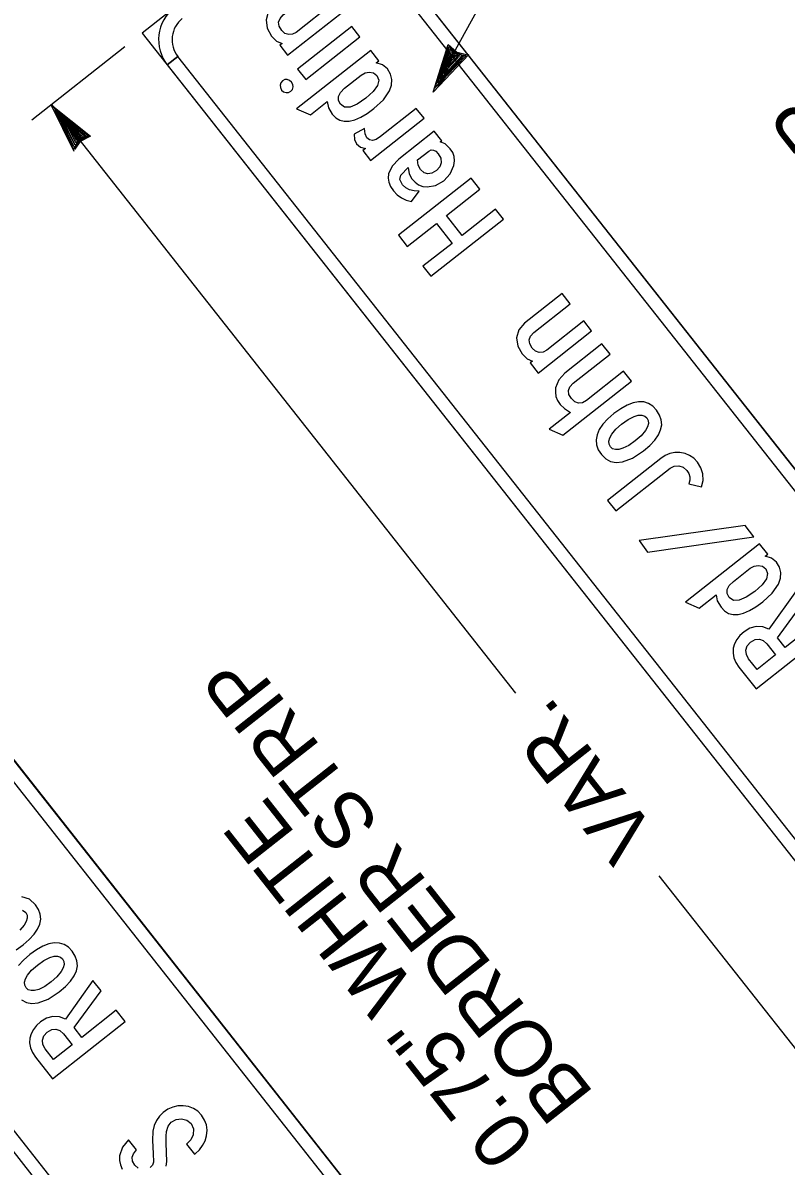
# Model space of a CAD drawing. Extents: x 672438 to 673980, y 1673259 to 1674850.
# Drawn here: x 673725.7 to 673782.3, y 1673411.9 to 1673496.8 of the extents above; entities that cross this region are included whole.
import ezdxf

# ---------------------------------------------------------------- set-up
doc = ezdxf.new("R2010")
doc.units = 0
doc.layers.add('C-ANNO-SYMB', color=7, linetype='Continuous')
doc.layers.add('Level 1', color=7, linetype='Continuous')

msp = doc.modelspace()

# ---------------------------------------------------------------- linework, layer by layer
at = {"layer": 'C-ANNO-SYMB'}
for p, q in [((673748.669, 1673507.161), (673734.534, 1673496.017)), ((673826.676, 1673408.211), (673748.669, 1673507.161)), ((673750.527, 1673504.805), (673824.819, 1673410.567)), ((673824.033, 1673409.948), (673749.741, 1673504.186)), ((673734.534, 1673496.017), (673812.54, 1673397.068)), ((673736.391, 1673493.661), (673737.176, 1673494.28)), ((673737.176, 1673494.28), (673736.391, 1673493.661)), ((673736.391, 1673493.661), (673810.683, 1673399.424)), ((673737.176, 1673494.28), (673737.176, 1673494.28)), ((673737.176, 1673494.28), (673737.176, 1673494.28)), ((673811.468, 1673400.043), (673737.176, 1673494.28)), ((673780.412, 1673371.74), (673702.406, 1673470.689)), ((673704.263, 1673468.333), (673778.555, 1673374.095)), ((673777.77, 1673373.476), (673703.478, 1673467.714)), ((673688.27, 1673459.545), (673766.277, 1673360.596)), ((673690.127, 1673457.189), (673764.42, 1673362.952)), ((673765.205, 1673363.571), (673690.913, 1673457.808))]:
    msp.add_line(p, q, dxfattribs=at)
for points in [[(673749.295, 1673497.493), (673748.712, 1673498.232), (673745.967, 1673496.068), (673745.695, 1673495.921), (673745.404, 1673495.895), (673745.127, 1673495.992), (673744.888, 1673496.206), (673744.703, 1673496.526), (673744.659, 1673496.827), (673744.76, 1673497.106), (673745.005, 1673497.367), (673747.712, 1673499.501), (673747.109, 1673500.265), (673744.318, 1673498.065), (673743.89, 1673497.575), (673743.721, 1673496.987), (673743.807, 1673496.366), (673744.134, 1673495.777), (673744.508, 1673495.419), (673744.91, 1673495.251), (673744.735, 1673495.113), (673745.326, 1673494.363)], [(673750.682, 1673495.733), (673750.082, 1673496.494), (673746.065, 1673493.328), (673746.665, 1673492.567)], [(673745.563, 1673491.698), (673745.682, 1673491.836), (673745.73, 1673492.014), (673745.711, 1673492.2), (673745.62, 1673492.37), (673745.475, 1673492.503), (673745.299, 1673492.57), (673745.119, 1673492.564), (673744.95, 1673492.476), (673744.825, 1673492.332), (673744.769, 1673492.152), (673744.788, 1673491.961), (673744.88, 1673491.786), (673745.028, 1673491.656), (673745.211, 1673491.599), (673745.399, 1673491.611)], [(673755.449, 1673489.687), (673754.866, 1673490.426), (673752.214, 1673488.324), (673751.904, 1673488.123), (673751.632, 1673488.04), (673751.401, 1673488.077), (673751.207, 1673488.236), (673751.07, 1673488.532), (673751.04, 1673488.926), (673750.272, 1673488.514), (673750.287, 1673488.105), (673750.424, 1673487.798), (673750.73, 1673487.543), (673751.093, 1673487.452), (673750.897, 1673487.297), (673751.48, 1673486.557)], [(673761.343, 1673482.21), (673760.76, 1673482.95), (673758.286, 1673480.999), (673757.119, 1673482.48), (673759.593, 1673484.43), (673758.943, 1673485.254), (673753.552, 1673481.004), (673754.202, 1673480.18), (673756.364, 1673481.885), (673757.531, 1673480.404), (673755.369, 1673478.7), (673755.952, 1673477.96)], [(673767.887, 1673473.91), (673767.304, 1673474.649), (673764.559, 1673472.485), (673764.286, 1673472.338), (673763.996, 1673472.312), (673763.718, 1673472.409), (673763.48, 1673472.624), (673763.295, 1673472.944), (673763.251, 1673473.244), (673763.351, 1673473.523), (673763.596, 1673473.784), (673766.303, 1673475.918), (673765.701, 1673476.682), (673762.909, 1673474.482), (673762.481, 1673473.992), (673762.313, 1673473.404), (673762.399, 1673472.783), (673762.726, 1673472.194), (673763.099, 1673471.836), (673763.502, 1673471.668), (673763.327, 1673471.53), (673763.918, 1673470.781)], [(673765.903, 1673470.78), (673765.441, 1673470.28), (673765.212, 1673469.689), (673765.193, 1673469.364), (673765.242, 1673469.049), (673765.363, 1673468.744), (673765.554, 1673468.451), (673765.873, 1673468.138), (673766.306, 1673467.853), (673764.729, 1673466.609), (673765.751, 1673466.165), (673770.834, 1673470.172), (673770.251, 1673470.911), (673767.505, 1673468.747), (673767.203, 1673468.57), (673766.914, 1673468.533), (673766.643, 1673468.635), (673766.386, 1673468.879), (673766.206, 1673469.19), (673766.164, 1673469.484), (673766.265, 1673469.759), (673766.505, 1673470.016), (673769.25, 1673472.18), (673768.648, 1673472.944)], [(673776.038, 1673462.33), (673776.161, 1673462.796), (673776.137, 1673463.288), (673775.995, 1673463.75), (673775.735, 1673464.171), (673775.465, 1673464.455), (673775.161, 1673464.67), (673774.821, 1673464.809), (673774.441, 1673464.879), (673774.059, 1673464.878), (673773.693, 1673464.803), (673773.345, 1673464.659), (673773.015, 1673464.443), (673769.064, 1673461.328), (673769.681, 1673460.546), (673773.71, 1673463.722), (673774.017, 1673463.878), (673774.36, 1673463.894), (673774.69, 1673463.782), (673774.951, 1673463.554), (673775.094, 1673463.324), (673775.168, 1673463.081), (673775.173, 1673462.826), (673775.109, 1673462.558)], [(673779.934, 1673458.628), (673779.274, 1673459.465), (673771.414, 1673458.347), (673772.03, 1673457.474)]]:
    msp.add_lwpolyline(points, close=True, dxfattribs=at)
for points in [[(673752.095, 1673493.951), (673751.491, 1673494.717), (673745.989, 1673490.379), (673747.01, 1673489.942), (673748.259, 1673490.926), (673748.346, 1673490.472), (673748.626, 1673490), (673748.894, 1673489.73), (673749.193, 1673489.553), (673749.529, 1673489.466), (673749.899, 1673489.474), (673750.306, 1673489.569), (673750.746, 1673489.759), (673751.222, 1673490.038), (673751.728, 1673490.408), (673752.432, 1673491.061), (673752.881, 1673491.721), (673753.036, 1673492.156), (673753.061, 1673492.573), (673752.961, 1673492.971), (673752.732, 1673493.349), (673752.362, 1673493.658), (673751.906, 1673493.801), (673752.095, 1673493.951)], [(673750.793, 1673492.898), (673751.075, 1673493.058), (673751.381, 1673493.114), (673751.7, 1673493.056), (673751.942, 1673492.861), (673752.085, 1673492.515), (673751.995, 1673492.119), (673751.679, 1673491.676), (673751.133, 1673491.181), (673750.497, 1673490.744), (673749.967, 1673490.521), (673749.551, 1673490.517), (673749.24, 1673490.73), (673749.091, 1673491.019), (673749.091, 1673491.314), (673749.242, 1673491.611), (673749.543, 1673491.913), (673750.793, 1673492.898)], [(673756.766, 1673488.016), (673756.209, 1673488.723), (673753.584, 1673486.654), (673753.078, 1673486.134), (673752.818, 1673485.574), (673752.791, 1673485.254), (673752.84, 1673484.939), (673752.968, 1673484.622), (673753.174, 1673484.311), (673753.455, 1673484.012), (673753.77, 1673483.782), (673754.124, 1673483.619), (673754.511, 1673483.522), (673755.083, 1673484.29), (673754.708, 1673484.291), (673754.374, 1673484.368), (673754.091, 1673484.523), (673753.855, 1673484.751), (673753.663, 1673485.133), (673753.722, 1673485.471), (673754.26, 1673486.04), (673754.342, 1673485.564), (673754.531, 1673485.198), (673754.778, 1673484.94), (673755.047, 1673484.754), (673755.347, 1673484.637), (673755.669, 1673484.588), (673756.304, 1673484.695), (673756.922, 1673485.054), (673757.399, 1673485.566), (673757.66, 1673486.182), (673757.71, 1673486.524), (673757.681, 1673486.846), (673757.579, 1673487.148), (673757.399, 1673487.43), (673757.022, 1673487.799), (673756.657, 1673487.93), (673756.766, 1673488.016)], [(673754.969, 1673486.599), (673755.799, 1673487.253), (673755.969, 1673487.339), (673756.142, 1673487.333), (673756.321, 1673487.236), (673756.502, 1673487.047), (673756.687, 1673486.721), (673756.721, 1673486.392), (673756.614, 1673486.083), (673756.365, 1673485.814), (673756.034, 1673485.615), (673755.728, 1673485.559), (673755.449, 1673485.649), (673755.191, 1673485.883), (673755.022, 1673486.206), (673754.969, 1673486.599)], [(673769.545, 1673467.768), (673769.083, 1673467.368), (673768.717, 1673466.972), (673768.454, 1673466.582), (673768.285, 1673466.2), (673768.22, 1673465.822), (673768.25, 1673465.452), (673768.382, 1673465.087), (673768.61, 1673464.731), (673768.931, 1673464.414), (673769.298, 1673464.218), (673769.712, 1673464.143), (673770.17, 1673464.188), (673770.929, 1673464.469), (673771.73, 1673464.996), (673772.201, 1673465.401), (673772.569, 1673465.796), (673772.842, 1673466.185), (673773.01, 1673466.566), (673773.085, 1673466.939), (673773.057, 1673467.305), (673772.931, 1673467.663), (673772.706, 1673468.014), (673772.42, 1673468.311), (673772.101, 1673468.517), (673771.753, 1673468.629), (673771.37, 1673468.646), (673770.963, 1673468.568), (673770.52, 1673468.396), (673770.05, 1673468.13), (673769.545, 1673467.768)], [(673770.114, 1673466.991), (673770.594, 1673467.327), (673771.045, 1673467.557), (673771.35, 1673467.645), (673771.61, 1673467.655), (673771.823, 1673467.589), (673771.987, 1673467.445), (673772.09, 1673467.25), (673772.104, 1673467.028), (673772.038, 1673466.78), (673771.881, 1673466.507), (673771.564, 1673466.123), (673771.129, 1673465.737), (673770.659, 1673465.409), (673770.212, 1673465.192), (673769.912, 1673465.104), (673769.653, 1673465.095), (673769.442, 1673465.162), (673769.275, 1673465.307), (673769.178, 1673465.498), (673769.161, 1673465.717), (673769.228, 1673465.961), (673769.374, 1673466.231), (673769.692, 1673466.612), (673770.114, 1673466.991)], [(673780.958, 1673457.339), (673780.353, 1673458.106), (673774.852, 1673453.768), (673775.872, 1673453.33), (673777.121, 1673454.315), (673777.208, 1673453.861), (673777.489, 1673453.389), (673777.757, 1673453.118), (673778.056, 1673452.942), (673778.392, 1673452.855), (673778.761, 1673452.863), (673779.168, 1673452.958), (673779.609, 1673453.147), (673780.085, 1673453.427), (673780.591, 1673453.797), (673781.294, 1673454.45), (673781.744, 1673455.109), (673781.899, 1673455.545), (673781.924, 1673455.962), (673781.824, 1673456.359), (673781.595, 1673456.738), (673781.225, 1673457.047), (673780.768, 1673457.19), (673780.958, 1673457.339)], [(673779.656, 1673456.287), (673779.938, 1673456.447), (673780.244, 1673456.503), (673780.563, 1673456.445), (673780.805, 1673456.249), (673780.947, 1673455.903), (673780.857, 1673455.508), (673780.542, 1673455.065), (673779.995, 1673454.57), (673779.359, 1673454.133), (673778.83, 1673453.91), (673778.413, 1673453.906), (673778.103, 1673454.119), (673777.953, 1673454.408), (673777.953, 1673454.703), (673778.105, 1673455), (673778.406, 1673455.301), (673779.656, 1673456.287)], [(673785.482, 1673451.591), (673784.815, 1673452.437), (673782.248, 1673450.413), (673781.681, 1673451.133), (673783.691, 1673453.862), (673783.082, 1673454.635), (673781.042, 1673451.757), (673780.59, 1673451.942), (673780.092, 1673451.962), (673779.633, 1673451.835), (673779.201, 1673451.575), (673778.895, 1673451.297), (673778.659, 1673450.998), (673778.495, 1673450.683), (673778.4, 1673450.352), (673778.381, 1673449.998), (673778.445, 1673449.646), (673778.591, 1673449.297), (673778.819, 1673448.954), (673780.09, 1673447.341), (673785.482, 1673451.591)], [(673781.538, 1673449.853), (673780.164, 1673448.77), (673779.54, 1673449.561), (673779.37, 1673449.876), (673779.334, 1673450.207), (673779.441, 1673450.522), (673779.688, 1673450.794), (673780.023, 1673450.988), (673780.333, 1673451.032), (673780.624, 1673450.927), (673780.894, 1673450.671), (673781.538, 1673449.853)], [(673725.177, 1673427.973), (673725.687, 1673428.34), (673726.143, 1673428.735), (673726.503, 1673429.123), (673726.766, 1673429.505), (673726.929, 1673429.879), (673726.998, 1673430.247), (673726.968, 1673430.608), (673726.841, 1673430.961), (673726.616, 1673431.311), (673726.157, 1673431.724), (673725.608, 1673431.909)], [(673725.66, 1673430.915), (673725.885, 1673430.735), (673725.989, 1673430.539), (673726.002, 1673430.319), (673725.931, 1673430.069), (673725.769, 1673429.798), (673725.451, 1673429.413)], [(673725.566, 1673424.255), (673725.933, 1673424.059), (673726.348, 1673423.985), (673726.806, 1673424.029), (673727.565, 1673424.31), (673728.366, 1673424.837), (673728.836, 1673425.242), (673729.205, 1673425.637), (673729.477, 1673426.026), (673729.646, 1673426.407), (673729.721, 1673426.78), (673729.692, 1673427.146), (673729.566, 1673427.504), (673729.341, 1673427.855), (673729.056, 1673428.152), (673728.736, 1673428.358), (673728.388, 1673428.47), (673728.006, 1673428.487), (673727.598, 1673428.41), (673727.155, 1673428.237), (673726.685, 1673427.971), (673726.18, 1673427.61)], [(673726.18, 1673427.61), (673725.719, 1673427.209), (673725.353, 1673426.814)], [(673726.749, 1673426.832), (673727.23, 1673427.168), (673727.681, 1673427.398), (673727.986, 1673427.486), (673728.245, 1673427.497), (673728.459, 1673427.43), (673728.623, 1673427.286), (673728.726, 1673427.091), (673728.74, 1673426.869), (673728.673, 1673426.621), (673728.516, 1673426.348), (673728.2, 1673425.964), (673727.765, 1673425.578), (673727.295, 1673425.25), (673726.848, 1673425.033), (673726.547, 1673424.945), (673726.288, 1673424.937), (673726.078, 1673425.004), (673725.91, 1673425.148), (673725.813, 1673425.339), (673725.796, 1673425.558), (673725.864, 1673425.802), (673726.01, 1673426.073), (673726.327, 1673426.454), (673726.749, 1673426.832)], [(673733.276, 1673422.647), (673732.61, 1673423.492), (673730.043, 1673421.469), (673729.475, 1673422.189), (673731.486, 1673424.917), (673730.877, 1673425.69), (673728.837, 1673422.812), (673728.385, 1673422.998), (673727.887, 1673423.018), (673727.428, 1673422.891), (673726.995, 1673422.631), (673726.689, 1673422.352), (673726.454, 1673422.053), (673726.289, 1673421.739), (673726.195, 1673421.408), (673726.176, 1673421.053), (673726.24, 1673420.701), (673726.386, 1673420.352), (673726.613, 1673420.01), (673727.885, 1673418.396), (673733.276, 1673422.647)], [(673729.333, 1673420.909), (673727.959, 1673419.825), (673727.335, 1673420.617), (673727.164, 1673420.931), (673727.128, 1673421.262), (673727.236, 1673421.578), (673727.483, 1673421.85), (673727.817, 1673422.044), (673728.127, 1673422.088), (673728.419, 1673421.983), (673728.689, 1673421.726), (673729.333, 1673420.909)], [(673736.308, 1673411.902), (673736.372, 1673412.247), (673736.308, 1673413.617), (673736.299, 1673414.137), (673736.324, 1673414.484), (673736.453, 1673414.874), (673736.692, 1673415.162), (673737.052, 1673415.36), (673737.444, 1673415.42), (673737.843, 1673415.322), (673738.154, 1673415.063), (673738.343, 1673414.674), (673738.324, 1673414.244), (673738.148, 1673413.861), (673737.83, 1673413.539), (673738.417, 1673412.794), (673738.467, 1673412.833), (673738.777, 1673413.115), (673739.019, 1673413.432), (673739.194, 1673413.784), (673739.303, 1673414.169), (673739.344, 1673414.579), (673739.294, 1673414.969), (673739.16, 1673415.334), (673738.938, 1673415.681), (673738.656, 1673415.979), (673738.331, 1673416.197), (673737.973, 1673416.335), (673737.573, 1673416.395), (673737.182, 1673416.378), (673736.805, 1673416.29), (673736.444, 1673416.132), (673736.096, 1673415.9), (673735.809, 1673415.623), (673735.583, 1673415.298), (673735.422, 1673414.924), (673735.322, 1673414.505), (673735.292, 1673413.822), (673735.356, 1673412.857), (673735.372, 1673412.198), (673735.285, 1673411.985), (673735.129, 1673411.813)], [(673734.23, 1673411.759), (673733.987, 1673411.972), (673733.821, 1673412.274), (673733.796, 1673412.571), (673733.896, 1673412.82), (673734.103, 1673413.113), (673733.512, 1673413.862), (673733.058, 1673413.307), (673732.85, 1673412.679), (673732.847, 1673412.337), (673732.911, 1673412.005), (673733.05, 1673411.677)]]:
    msp.add_lwpolyline(points, dxfattribs=at)
for radius in [3, 2]:
    msp.add_arc((673738.747, 1673495.518), radius, 128.25054, 218.25075, dxfattribs=at)
at = {"layer": 'Level 1'}
for p, q in [((673756.128, 1673491.622), (673757.245, 1673495.172)), ((673757.245, 1673495.172), (673757.884, 1673494.605)), ((673733.247, 1673494.982), (673726.342, 1673489.539)), ((673758.783, 1673494.422), (673756.128, 1673491.622)), ((673756.246, 1673491.921), (673757.281, 1673495.027)), ((673758.414, 1673494.317), (673756.274, 1673491.966)), ((673758.582, 1673494.341), (673756.391, 1673492.109)), ((673756.475, 1673492.305), (673757.339, 1673494.869)), ((673756.643, 1673492.477), (673757.475, 1673494.637)), ((673758.275, 1673494.341), (673756.643, 1673492.477)), ((673756.665, 1673492.618), (673757.388, 1673494.747)), ((673758.275, 1673494.341), (673756.665, 1673492.618)), ((673756.947, 1673493.091), (673757.475, 1673494.483)), ((673758.087, 1673494.331), (673756.947, 1673493.091)), ((673757.212, 1673493.481), (673757.488, 1673494.351)), ((673757.921, 1673494.309), (673757.212, 1673493.481)), ((673757.281, 1673495.027), (673757.803, 1673494.623)), ((673757.525, 1673494.516), (673757.327, 1673493.626)), ((673757.339, 1673494.869), (673757.562, 1673494.676)), ((673757.388, 1673494.747), (673758.275, 1673494.341)), ((673757.803, 1673494.317), (673757.418, 1673493.878)), ((673757.475, 1673494.637), (673758.087, 1673494.331)), ((673757.475, 1673494.483), (673757.921, 1673494.309)), ((673757.488, 1673494.351), (673757.803, 1673494.317)), ((673757.974, 1673494.398), (673757.525, 1673494.516)), ((673757.562, 1673494.676), (673758.275, 1673494.341)), ((673757.644, 1673494.259), (673757.974, 1673494.398)), ((673757.803, 1673494.623), (673758.599, 1673494.423)), ((673757.884, 1673494.605), (673758.221, 1673494.403)), ((673758.221, 1673494.403), (673758.582, 1673494.341)), ((673758.372, 1673494.403), (673758.414, 1673494.317)), ((673757.327, 1673493.626), (673757.127, 1673493.441)), ((673757.418, 1673493.878), (673757.544, 1673494.29)), ((673757.544, 1673494.29), (673757.644, 1673494.259)), ((673756.457, 1673492.068), (673757.049, 1673492.752)), ((673757.049, 1673492.752), (673756.475, 1673492.305)), ((673757.127, 1673493.441), (673756.915, 1673492.986)), ((673756.915, 1673492.986), (673757.246, 1673493.337)), ((673729.49, 1673487.216), (673727.787, 1673490.678)), ((673727.787, 1673490.678), (673730.695, 1673488.356)), ((673762.257, 1673447.023), (673727.82, 1673490.704)), ((673728.146, 1673490.257), (673728.023, 1673490.46)), ((673728.023, 1673490.46), (673730.547, 1673488.375)), ((673729.476, 1673487.574), (673728.054, 1673490.418)), ((673728.054, 1673490.418), (673728.084, 1673490.211)), ((673728.084, 1673490.211), (673728.509, 1673489.411)), ((673729.438, 1673487.408), (673728.146, 1673490.257)), ((673728.509, 1673489.411), (673728.298, 1673490.109)), ((673728.298, 1673490.109), (673730.378, 1673488.377)), ((673729.548, 1673487.695), (673728.398, 1673489.89)), ((673728.398, 1673489.89), (673730.113, 1673488.335)), ((673729.548, 1673487.695), (673728.522, 1673489.818)), ((673728.522, 1673489.818), (673730.247, 1673488.376)), ((673729.123, 1673489.091), (673728.775, 1673489.452)), ((673728.775, 1673489.452), (673728.983, 1673489.017)), ((673729.607, 1673487.874), (673728.861, 1673489.384)), ((673728.861, 1673489.384), (673729.969, 1673488.39)), ((673729.223, 1673488.837), (673729.123, 1673489.091)), ((673729.647, 1673488.037), (673729.13, 1673488.997)), ((673729.13, 1673488.997), (673729.842, 1673488.425)), ((673729.981, 1673488.331), (673729.223, 1673488.837)), ((673729.696, 1673488.144), (673729.425, 1673488.661)), ((673729.425, 1673488.661), (673729.765, 1673488.395)), ((673730.247, 1673488.376), (673729.548, 1673487.695)), ((673729.969, 1673488.39), (673729.647, 1673488.037)), ((673729.842, 1673488.425), (673729.696, 1673488.144)), ((673729.765, 1673488.395), (673729.7, 1673488.313)), ((673730.547, 1673488.375), (673729.981, 1673488.034)), ((673730.378, 1673488.377), (673730.118, 1673488.239)), ((673729.626, 1673487.723), (673729.438, 1673487.408)), ((673729.572, 1673487.582), (673729.476, 1673487.574)), ((673729.981, 1673488.034), (673729.508, 1673487.363)), ((673730.118, 1673488.239), (673729.548, 1673487.695)), ((673730.113, 1673488.335), (673729.607, 1673487.874)), ((673729.936, 1673487.964), (673729.626, 1673487.723)), ((673729.7, 1673488.313), (673729.71, 1673487.956)), ((673729.71, 1673487.956), (673729.981, 1673488.331)), ((673730.695, 1673488.356), (673729.936, 1673487.964)), ((673805.784, 1673391.741), (673772.9, 1673433.453))]:
    msp.add_line(p, q, dxfattribs=at)
msp.add_lwpolyline([(673757.266, 1673493.83), (673763.428, 1673505.007), (673760.682, 1673508.49)], dxfattribs=at)

# ---------------------------------------------------------------- texts
for s, p in [('BORDER STRIP', (673810.262, 1673459.148)), ('BORDER STRIP', (673768.137, 1673417.279)), ('VAR.', (673772.81, 1673436.617)), ('0.75" WHITE ', (673763.843, 1673413.894))]:
    msp.add_text(s, height=4.2, rotation=128.25054, dxfattribs=at).set_placement(p)

doc.saveas('drawing.dxf')
